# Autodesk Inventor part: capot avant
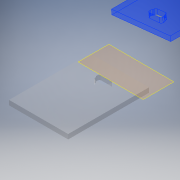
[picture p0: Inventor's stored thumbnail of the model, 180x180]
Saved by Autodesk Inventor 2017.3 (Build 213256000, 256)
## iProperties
Part Number: capot avant
Material: Plastique PMMA
Document SubType Name: Modeling
Designer: ficho
Mass: 6.87099 g
Surface Area: 44.667 cm^2
Volume: 5.78366 cm^3
Density: 1.188 g/cm^3
Appearance: Polycarbonate - Transparent
Author: ficho
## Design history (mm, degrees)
node "Plan de construction1"
sketch "Esquisse1"
  geometry: L1 (40.9, 0)-(3, 0) reference; L2 (3, 0)-(40.9, 0); L3 (40.9, 0)-(40.9, -65); L4 (40.9, -65)-(3, -65); L5 (3, -65)-(3, 0); L6 (18.265, -25.25)-(18.265, -24.58); L7 (18.265, -24.58)-(18.093, -24.452); L8 (17.65, -23.57)-(17.65, -22.75); L9 (18.75, -21.65)-(25.25, -21.65); L10 (26.35, -22.75)-(26.35, -23.57); L11 (25.907, -24.452)-(25.735, -24.58); L12 (25.735, -24.58)-(25.735, -25.25); L13 (24.635, -26.35)-(19.365, -26.35); L14 (25.7, -17.9)-(25.7, -7); L15 (25.2, -6.5)-(16.2, -6.5); L16 (15.7, -7)-(15.7, -17.9); L17 (16.2, -18.4)-(25.2, -18.4); A1 r 1.1 centre (19.365, -25.25) between (18.265, -25.25) and (19.365, -26.35); A2 r 1.1 centre (18.75, -23.57) between (17.65, -23.57) and (18.093, -24.452); A3 r 1.1 centre (18.75, -22.75) between (18.75, -21.65) and (17.65, -22.75); A4 r 1.1 centre (25.25, -22.75) between (26.35, -22.75) and (25.25, -21.65); A5 r 1.1 centre (25.25, -23.57) between (25.907, -24.452) and (26.35, -23.57); A6 r 1.1 centre (24.635, -25.25) between (24.635, -26.35) and (25.735, -25.25); A7 r 0.5 centre (25.2, -7) between (25.7, -7) and (25.2, -6.5); A8 r 0.5 centre (16.2, -7) between (16.2, -6.5) and (15.7, -7); A9 r 0.5 centre (16.2, -17.9) between (15.7, -17.9) and (16.2, -18.4); A10 r 0.5 centre (25.2, -17.9) between (25.2, -18.4) and (25.7, -17.9); 1 further point
  constraints: 32 end point, 20 point on circle, 10 centre point, 8 tangent, 3 equal radius, 2 parallel, 1 horizontal, 1 perpendicular, 1 other
  dimensions: "d2" = 0.5 radius of A7; "d5" = 38.65 distance between parallel lines of L13 L4; "d6" = 1.1 radius of A1; "d7" = 1.1 radius of A6; "d8" = 1.1 radius of A5; "d9" = 1.1 radius of A4; "d10" = 1.1 radius of A3; "d11" = 1.1 radius of A2; "d12" = 4.7 distance between parallel lines of L9 L13; "d13" = 8.7 distance between parallel lines of L8 L10; "d14" = 7.47 distance of L6.end L11.end; "d15" = 1.1 distance from line of A6.centre L13; "d16" = 1.1 distance from line of A1.centre L13; "d17" = 2.78 distance from line of A2.centre L13; "d18" = 3.6 distance from line of L13 A3.centre; "d19" = 3.6 distance from line of L13 A4.centre; "d20" = 2.78 distance from line of L13 A5.centre
extrude "Extrusion1" new body sketch "Esquisse1" distance "d3" = 3; taper "d4" = 0 deg
sketch "Esquisse2"
  geometry: L1 (0, -13.148)-(9.601, -13.148) reference; L2 (0, -13.148)-(45.389, -13.148); L3 (45.389, -13.148)-(45.389, 2.58); L4 (45.389, 2.58)-(0, 2.58); L5 (0, 2.58)-(0, -13.148); 1 further point
  constraints: 10 end point, 2 horizontal, 2 parallel, 1 perpendicular, 2 other
extrude "Extrusion2" cut sketch "Esquisse2" stored distance "d21" = 10; taper "d22" = 0 deg
sketch "Esquisse3"
  geometry: L1 (25.2, -18.4)-(16.2, -18.4) reference; L2 (15.7, -13.148)-(26.016, -13.148); L3 (26.016, -13.148)-(26.016, -18.4); L4 (26.016, -18.4)-(15.7, -18.4); L5 (15.7, -18.4)-(15.7, -13.148); 1 further point
  constraints: 8 end point, 2 parallel, 1 horizontal, 1 perpendicular
extrude "Extrusion3" join sketch "Esquisse3" distance "d23" = 3; taper "d24" = 0 deg
node "Solide1"
node "Référence1"
